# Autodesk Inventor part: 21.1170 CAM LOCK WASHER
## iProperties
Created: 2007-03
Part Number: 21.1170 CAM LOCK WASHER
Document SubType Name: Modeling
Designer: Andy Moles
Material: Steel
Mass: 0.239394 g
Surface Area: 1.23593 cm^2
Volume: 0.030496 cm^3
Density: 7.85 g/cm^3
Author: Andy Moles
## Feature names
1. Base1
